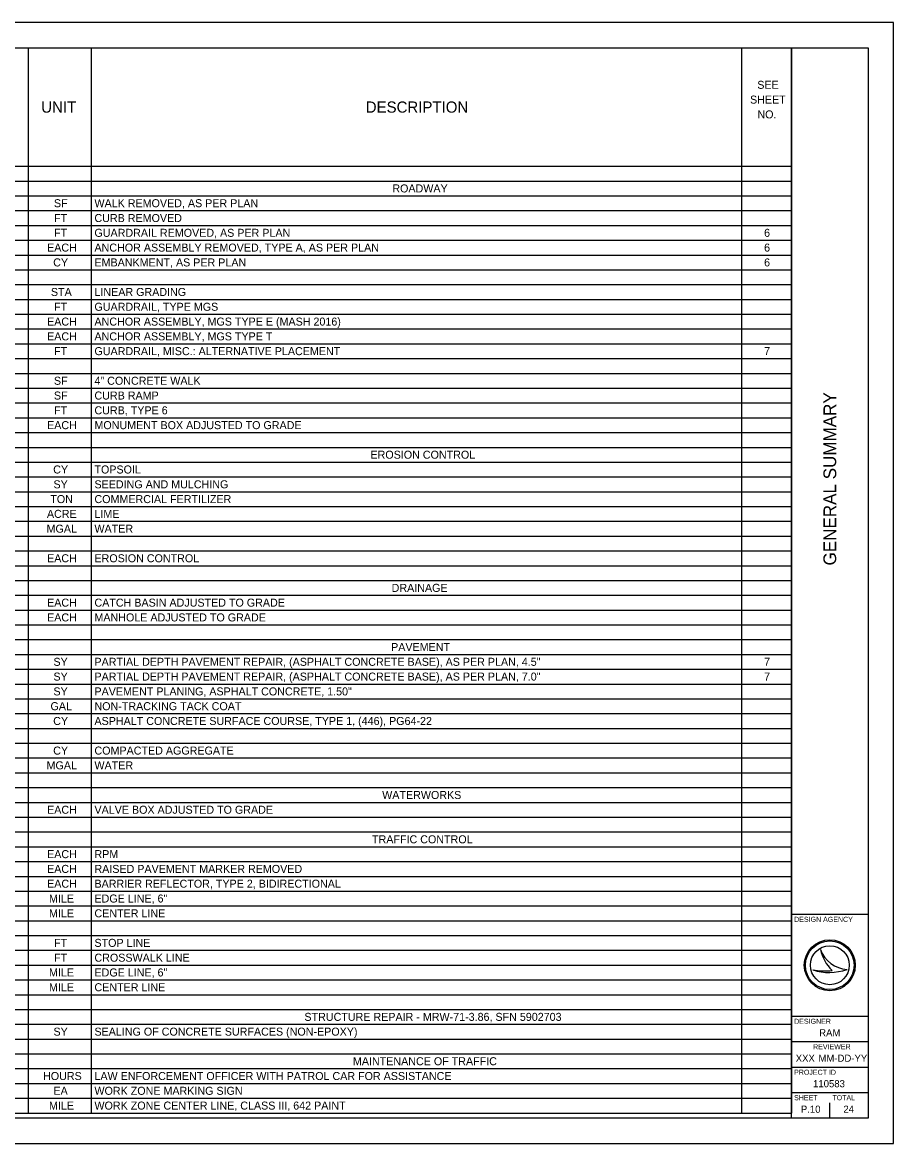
# Model space of a CAD drawing. Extents: x 0 to 34, y 0 to 22.
# Drawn here: x 16.92 to 34, y 0 to 22 of the extents above; entities that cross this region are included whole.
import ezdxf

# ---------------------------------------------------------------- set-up
doc = ezdxf.new("R2010")
doc.units = 0
for name, color, linetype in [('Default', 7, 'Continuous'), ('SH_Border', 7, 'Continuous'), ('SH_Cut_Line', 7, 'Continuous'), ('SH_Data', 7, 'Continuous')]:
    doc.layers.add(name, color=color, linetype=linetype)

msp = doc.modelspace()

# ---------------------------------------------------------------- linework, layer by layer
at = {"layer": 'Default'}
for p, q in [((1.5, 21.5), (32, 21.5)), ((17.028, 21.5), (17.028, 0.6)), ((18.265, 21.5), (18.265, 0.6)), ((31.017, 21.5), (31.017, 0.6)), ((32, 21.5), (32, 0.6)), ((1.5, 19.178), (32, 19.178)), ((1.5, 18.887), (32, 18.887)), ((1.5, 18.597), (32, 18.597)), ((1.5, 18.307), (32, 18.307)), ((1.5, 18.017), (32, 18.017)), ((1.5, 17.726), (32, 17.726)), ((1.5, 17.436), (32, 17.436)), ((1.5, 17.146), (32, 17.146)), ((1.5, 16.856), (32, 16.856)), ((1.5, 16.565), (32, 16.565)), ((1.5, 16.275), (32, 16.275)), ((1.5, 15.985), (32, 15.985)), ((1.5, 15.694), (32, 15.694)), ((1.5, 15.404), (32, 15.404)), ((1.5, 15.114), (32, 15.114)), ((1.5, 14.824), (32, 14.824)), ((1.5, 14.533), (32, 14.533)), ((1.5, 14.243), (32, 14.243)), ((1.5, 13.953), (32, 13.953)), ((1.5, 13.662), (32, 13.662)), ((1.5, 13.372), (32, 13.372)), ((1.5, 13.082), (32, 13.082)), ((1.5, 12.792), (32, 12.792)), ((1.5, 12.501), (32, 12.501)), ((1.5, 12.211), (32, 12.211)), ((1.5, 11.921), (32, 11.921)), ((1.5, 11.631), (32, 11.631)), ((1.5, 11.34), (32, 11.34)), ((1.5, 11.05), (32, 11.05)), ((1.5, 10.76), (32, 10.76)), ((1.5, 10.469), (32, 10.469)), ((1.5, 10.179), (32, 10.179)), ((1.5, 9.889), (32, 9.889)), ((1.5, 9.599), (32, 9.599)), ((1.5, 9.308), (32, 9.308)), ((1.5, 9.018), (32, 9.018)), ((1.5, 8.728), (32, 8.728)), ((1.5, 8.438), (32, 8.438)), ((1.5, 8.147), (32, 8.147)), ((1.5, 7.857), (32, 7.857)), ((1.5, 7.567), (32, 7.567)), ((1.5, 7.276), (32, 7.276)), ((1.5, 6.986), (32, 6.986)), ((1.5, 6.696), (32, 6.696)), ((1.5, 6.406), (32, 6.406)), ((1.5, 6.115), (32, 6.115)), ((1.5, 5.825), (32, 5.825)), ((1.5, 5.535), (32, 5.535)), ((1.5, 5.244), (32, 5.244)), ((1.5, 4.954), (32, 4.954)), ((1.5, 4.664), (32, 4.664)), ((1.5, 4.374), (32, 4.374)), ((1.5, 4.083), (32, 4.083)), ((1.5, 3.793), (32, 3.793)), ((1.5, 3.503), (32, 3.503)), ((1.5, 3.212), (32, 3.212)), ((1.5, 2.922), (32, 2.922)), ((1.5, 2.632), (32, 2.632)), ((1.5, 2.342), (32, 2.342)), ((1.5, 2.051), (32, 2.051)), ((1.5, 1.761), (32, 1.761)), ((1.5, 1.471), (32, 1.471)), ((1.5, 1.181), (32, 1.181)), ((1.5, 0.89), (32, 0.89)), ((1.5, 0.6), (32, 0.6))]:
    msp.add_line(p, q, dxfattribs=at)
at = {"layer": 'SH_Border'}
for p, q in [((32, 0.5), (32, 21.5)), ((32, 4.5), (33.5, 4.5)), ((32, 2.5), (33.5, 2.5)), ((32, 2), (33.5, 2)), ((32, 1.5), (33.5, 1.5)), ((32, 1), (33.5, 1))]:
    msp.add_line(p, q, dxfattribs=at)
msp.add_lwpolyline([(1.5, 21.5), (33.5, 21.5), (33.5, 0.5), (1.5, 0.5)], close=True, dxfattribs=at)
at = {"layer": 'SH_Cut_Line'}
msp.add_lwpolyline([(0, 0), (34, 0), (34, 22), (0, 22)], close=True, dxfattribs=at)
at = {"layer": 'SH_Data'}
for p, q in [((32.567, 3.81), (32.567, 3.81)), ((32.417, 3.41), (32.417, 3.41)), ((32.75, 3.5), (32.75, 3.5)), ((33.087, 3.419), (33.087, 3.419)), ((32.375, 0.675), (32.375, 0.675)), ((32.75, 0.5), (32.75, 0.8))]:
    msp.add_line(p, q, dxfattribs=at)
for radius in [0.5, 0.477, 0.477, 0.382]:
    msp.add_circle((32.75, 3.5), radius, dxfattribs=at)
for centre, radius, start, end in [((33.116, 3.998), 0.58, 198.9257, 198.9319), ((33.347, 3.97), 0.796, 191.6379, 191.6421), ((33.116, 3.998), 0.58, 198.9319, 267.1657), ((33.347, 3.97), 0.796, 191.6421, 226.0947), ((32.739, 4.37), 1.013, 251.4576, 290.0832), ((32.648, 4.654), 1.266, 259.4964, 259.4995), ((32.739, 4.37), 1.013, 251.4527, 251.4576), ((32.648, 4.654), 1.266, 259.4995, 276.6672)]:
    msp.add_arc(centre, radius, start, end, dxfattribs=at)

# ---------------------------------------------------------------- texts
at = {"layer": 'Default'}
for s, height, p in [('SEE', 0.1571, (31.327, 20.697)), ('SHEET', 0.1571, (31.185, 20.407)), ('UNIT', 0.2199, (17.284, 20.229)), ('DESCRIPTION', 0.21993, (23.649, 20.229)), ('NO.', 0.1571, (31.33, 20.117)), ('ROADWAY', 0.1571, (24.17, 18.664)), ('SF', 0.1571, (17.533, 18.374)), ('WALK REMOVED, AS PER PLAN', 0.15709, (18.328, 18.374)), ('FT', 0.1571, (17.536, 18.083)), ('CURB REMOVED', 0.15709, (18.328, 18.083)), ('FT', 0.1571, (17.536, 17.793)), ('GUARDRAIL REMOVED, AS PER PLAN', 0.15709, (18.328, 17.793)), ('6', 0.157, (31.461, 17.793)), ('EACH', 0.1571, (17.399, 17.503)), ('ANCHOR ASSEMBLY REMOVED, TYPE A, AS PER PLAN', 0.15709, (18.328, 17.503)), ('6', 0.157, (31.461, 17.503)), ('CY', 0.1571, (17.519, 17.212)), ('EMBANKMENT, AS PER PLAN', 0.15709, (18.328, 17.212)), ('6', 0.157, (31.461, 17.212)), ('STA', 0.1571, (17.474, 16.632)), ('LINEAR GRADING', 0.15709, (18.328, 16.632)), ('GUARDRAIL, TYPE MGS', 0.15709, (18.328, 16.342)), ('FT', 0.1571, (17.536, 16.342)), ('EACH', 0.1571, (17.399, 16.051)), ('ANCHOR ASSEMBLY, MGS TYPE E (MASH 2016)', 0.15709, (18.328, 16.051)), ('EACH', 0.1571, (17.399, 15.761)), ('ANCHOR ASSEMBLY, MGS TYPE T', 0.15709, (18.328, 15.761)), ('FT', 0.1571, (17.536, 15.471)), ('GUARDRAIL, MISC.: ALTERNATIVE PLACEMENT', 0.15709, (18.328, 15.471)), ('7', 0.157, (31.461, 15.471)), ('SF', 0.1571, (17.533, 14.89)), ('4" CONCRETE WALK', 0.15709, (18.328, 14.89)), ('SF', 0.1571, (17.533, 14.6)), ('CURB RAMP', 0.1571, (18.328, 14.6)), ('FT', 0.1571, (17.536, 14.31)), ('CURB, TYPE 6', 0.15709, (18.328, 14.31)), ('EACH', 0.1571, (17.399, 14.019)), ('MONUMENT BOX ADJUSTED TO GRADE', 0.15709, (18.328, 14.019)), ('EROSION CONTROL', 0.15709, (23.741, 13.439)), ('CY', 0.1571, (17.519, 13.149)), ('TOPSOIL', 0.1571, (18.328, 13.149)), ('SY', 0.1571, (17.524, 12.858)), ('SEEDING AND MULCHING', 0.15709, (18.328, 12.858)), ('TON', 0.1571, (17.462, 12.568)), ('COMMERCIAL FERTILIZER', 0.15709, (18.328, 12.568)), ('ACRE', 0.1571, (17.396, 12.278)), ('LIME', 0.1571, (18.328, 12.278)), ('MGAL', 0.1571, (17.389, 11.987)), ('WATER', 0.1571, (18.328, 11.987)), ('EACH', 0.1571, (17.399, 11.407)), ('EROSION CONTROL', 0.15709, (18.328, 11.407)), ('DRAINAGE', 0.1571, (24.156, 10.826)), ('EACH', 0.1571, (17.399, 10.536)), ('CATCH BASIN ADJUSTED TO GRADE', 0.15709, (18.328, 10.536)), ('EACH', 0.1571, (17.399, 10.246)), ('MANHOLE ADJUSTED TO GRADE', 0.15709, (18.328, 10.246)), ('PAVEMENT', 0.1571, (24.146, 9.665)), ('SY', 0.1571, (17.524, 9.375)), ('PARTIAL DEPTH PAVEMENT REPAIR, (ASPHALT CONCRETE BASE), AS PER PLAN, 4.5"', 0.15709, (18.328, 9.375)), ('7', 0.157, (31.461, 9.375)), ('SY', 0.1571, (17.524, 9.085)), ('PARTIAL DEPTH PAVEMENT REPAIR, (ASPHALT CONCRETE BASE), AS PER PLAN, 7.0"', 0.15709, (18.328, 9.085)), ('7', 0.157, (31.461, 9.085)), ('SY', 0.1571, (17.524, 8.794)), ('PAVEMENT PLANING, ASPHALT CONCRETE, 1.50"', 0.15709, (18.328, 8.794)), ('GAL', 0.1571, (17.466, 8.504)), ('NON-TRACKING TACK COAT', 0.15709, (18.328, 8.504)), ('CY', 0.1571, (17.519, 8.214)), ('ASPHALT CONCRETE SURFACE COURSE, TYPE 1, (446), PG64-22', 0.15709, (18.328, 8.214)), ('CY', 0.1571, (17.519, 7.633)), ('COMPACTED AGGREGATE', 0.15709, (18.328, 7.633)), ('MGAL', 0.1571, (17.389, 7.343)), ('WATER', 0.1571, (18.328, 7.343)), ('WATERWORKS', 0.1571, (23.971, 6.762)), ('EACH', 0.1571, (17.399, 6.472)), ('VALVE BOX ADJUSTED TO GRADE', 0.15709, (18.328, 6.472)), ('TRAFFIC CONTROL', 0.15709, (23.772, 5.892)), ('EACH', 0.1571, (17.399, 5.601)), ('RPM', 0.1571, (18.328, 5.601)), ('EACH', 0.1571, (17.399, 5.311)), ('RAISED PAVEMENT MARKER REMOVED', 0.15709, (18.328, 5.311)), ('EACH', 0.1571, (17.399, 5.021)), ('BARRIER REFLECTOR, TYPE 2, BIDIRECTIONAL', 0.15709, (18.328, 5.021)), ('MILE', 0.1571, (17.437, 4.73)), ('EDGE LINE, 6"', 0.15709, (18.328, 4.73)), ('MILE', 0.1571, (17.437, 4.44)), ('CENTER LINE', 0.15709, (18.328, 4.44)), ('FT', 0.1571, (17.536, 3.86)), ('STOP LINE', 0.1571, (18.328, 3.86)), ('FT', 0.1571, (17.536, 3.569)), ('CROSSWALK LINE', 0.15709, (18.328, 3.569)), ('MILE', 0.1571, (17.437, 3.279)), ('EDGE LINE, 6"', 0.15709, (18.328, 3.279)), ('MILE', 0.1571, (17.437, 2.989)), ('CENTER LINE', 0.15709, (18.328, 2.989)), ('STRUCTURE REPAIR - MRW-71-3.86, SFN 5902703', 0.15709, (22.446, 2.408)), ('SY', 0.1571, (17.524, 2.118)), ('SEALING OF CONCRETE SURFACES (NON-EPOXY)', 0.15709, (18.328, 2.118)), ('MAINTENANCE OF TRAFFIC', 0.15709, (23.397, 1.537)), ('HOURS', 0.1571, (17.32, 1.247)), ('LAW ENFORCEMENT OFFICER WITH PATROL CAR FOR ASSISTANCE', 0.15709, (18.328, 1.247)), ('EA', 0.1571, (17.524, 0.957)), ('WORK ZONE MARKING SIGN', 0.15709, (18.328, 0.957)), ('MILE', 0.1571, (17.437, 0.667)), ('WORK ZONE CENTER LINE, CLASS III, 642 PAINT', 0.15709, (18.328, 0.667))]:
    msp.add_text(s, height=height, dxfattribs=at).set_placement(p)
at = {"layer": 'SH_Data'}
msp.add_text('GENERAL SUMMARY', height=0.25, rotation=90, dxfattribs=at).set_placement((32.875, 11.344))
for s, height, p in [('DESIGN AGENCY', 0.1, (32.05, 4.35)), ('DESIGNER', 0.1, (32.05, 2.35)), ('RAM', 0.14, (32.541, 2.105)), ('REVIEWER', 0.1, (32.422, 1.85)), ('XXX', 0.14, (32.081, 1.605)), ('MM-DD-YY', 0.14, (32.527, 1.605)), ('PROJECT ID', 0.1, (32.05, 1.35)), ('110583', 0.14, (32.421, 1.105)), ('SHEET', 0.1, (32.05, 0.85)), ('TOTAL', 0.1, (32.8, 0.85)), ('P.10', 0.14, (32.182, 0.605)), ('24', 0.14, (33.016, 0.605))]:
    msp.add_text(s, height=height, dxfattribs=at).set_placement(p)

doc.saveas('drawing.dxf')
